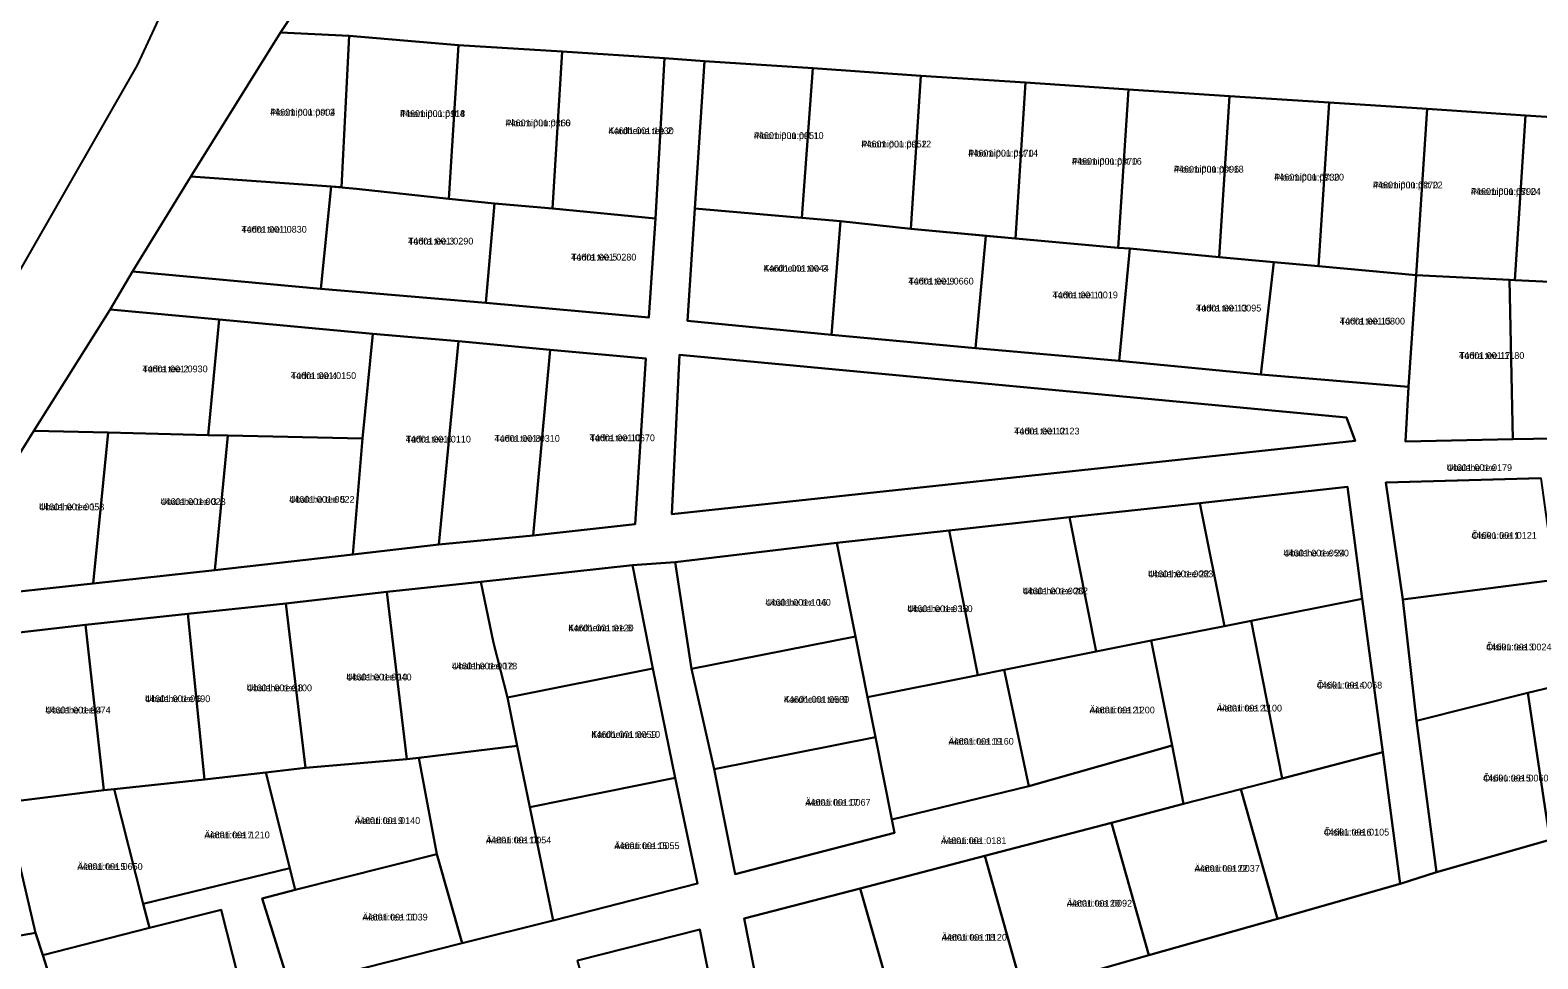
# Model space of a CAD drawing. Extents: x 551843 to 558501, y 6589003 to 6595718.
# Drawn here: x 552686.3 to 553021.3, y 6594140 to 6594346.2 of the extents above; entities that cross this region are included whole.
import ezdxf

# ---------------------------------------------------------------- set-up
doc = ezdxf.new("R2010")
doc.units = 0
for name, color, linetype in [('L_AADRESS', 7, 'Continuous'), ('PIIR', 7, 'Continuous'), ('TUNNUS', 7, 'Continuous')]:
    doc.layers.add(name, color=color, linetype=linetype)

msp = doc.modelspace()

# ---------------------------------------------------------------- linework, layer by layer
at = {"layer": 'PIIR'}
for points in [[(552676.63, 6594279.98), (552710.18, 6594338.44), (552745.65, 6594415), (552793.72, 6594491.36), (552795.61, 6594502.88), (552792.17, 6594519.71), (552781.04, 6594550.55), (552814.3, 6594546.07), (552818.23, 6594527.03), (552823.06, 6594503.42), (552821.12, 6594491.82), (552810.12, 6594492.3), (552808.89, 6594461.57), (552795.93, 6594432.53), (552789.98, 6594427.46), (552788.3, 6594424.19), (552772.33, 6594393.24), (552758.25, 6594370.36), (552741.94, 6594345.71), (552722.08, 6594313.72), (552709.1, 6594292.61), (552704.13, 6594284.19), (552687.17, 6594257.22), (552674.48, 6594236.93)], [(553194.56, 6594276.53), (553173.93, 6594295.82), (553163.41, 6594306.08), (553147.91, 6594313.18), (553121.76, 6594320.3), (553090.15, 6594322.85), (553081.55, 6594323.18), (553062.89, 6594324.4), (553040.63, 6594325.85), (553018.57, 6594327.29), (552996.74, 6594328.72), (552974.97, 6594330.15), (552952.85, 6594331.6), (552930.37, 6594333.07), (552907.51, 6594334.57), (552884.27, 6594336.09), (552860.25, 6594337.8), (552836.15, 6594339.37), (552827.27, 6594340.04), (552804.55, 6594341.5), (552781.49, 6594342.87), (552757.25, 6594344.93), (552741.94, 6594345.71), (552758.25, 6594370.36)], [(552672.97, 6594220.35), (552700.37, 6594223.36), (552727.41, 6594226.33), (552758.07, 6594229.78), (552777.16, 6594232.02), (552798.13, 6594234.04), (552820.77, 6594236.53), (552823.17, 6594273.31), (552801.89, 6594275.26), (552781.48, 6594277.15), (552762.5, 6594278.78), (552728.31, 6594281.97), (552704.13, 6594284.19), (552709.1, 6594292.61), (552750.9, 6594288.79), (552787.58, 6594285.7), (552823.82, 6594282.39), (552825.3, 6594304.42), (552827.27, 6594340.04), (552836.15, 6594339.37), (552834.01, 6594306.61), (552832.38, 6594281.68), (552864.38, 6594278.57), (552896.38, 6594275.64), (552928.3, 6594272.79), (552959.79, 6594269.78), (552992.57, 6594267.01), (552991.89, 6594254.86), (553015.76, 6594255.38), (553038.61, 6594255.8)], [(553021.95, 6594246.77), (552987.53, 6594245.76), (552991.31, 6594219.76), (552994.34, 6594192.86), (552998.81, 6594159.24), (552990.77, 6594156.63), (552986.85, 6594185.88), (552982.31, 6594219.97), (552979.01, 6594244.8), (552946.25, 6594241.21), (552917.26, 6594238.04), (552890.52, 6594235.11), (552865.58, 6594232.37), (552829.65, 6594228.1), (552820.14, 6594227.42), (552786.48, 6594223.71), (552765.56, 6594221.47), (552743.13, 6594218.88), (552721.39, 6594216.61), (552698.65, 6594214.16), (552676.78, 6594211.68)], [(552733.81, 6594131.03), (552728.76, 6594150.9), (552712.85, 6594146.86), (552711.49, 6594152.19), (552744.01, 6594160.13), (552745.23, 6594155.3), (552737.93, 6594153.38), (552744.04, 6594133.78), (552782.31, 6594143.47), (552802.57, 6594148.5), (552834.58, 6594156.74), (552829.69, 6594180.22), (552824.71, 6594204.46), (552820.14, 6594227.42), (552829.65, 6594228.1), (552833.25, 6594204.43), (552838.35, 6594182.13), (552842.99, 6594158.76), (552878.37, 6594167.95), (552877.79, 6594170.9), (552908.22, 6594178.34), (552940.07, 6594187.35), (552942.6, 6594174.38), (552926.59, 6594170.18), (552898.42, 6594162.84), (552870.79, 6594155.65), (552844.95, 6594148.93), (552851.28, 6594117.04)], [(552673.17, 6594066.67), (552696.67, 6594073.28), (552719.97, 6594079.85), (552744.27, 6594086.95), (552767.72, 6594093.6), (552792.38, 6594100.78), (552817.06, 6594107.42), (552841.54, 6594114.37), (552851.28, 6594117.04), (552879.47, 6594125.05), (552906.93, 6594132.82), (552934.92, 6594140.78), (552963.51, 6594148.89), (552990.77, 6594156.63), (552998.81, 6594159.24), (553024.01, 6594166.39)], [(552841.54, 6594114.37), (552835.14, 6594146.54), (552807.92, 6594139.61)]]:
    msp.add_lwpolyline(points, dxfattribs=at)
for points in [[(552757.25, 6594344.93), (552755.53, 6594311.35), (552753.23, 6594311.53), (552722.08, 6594313.72), (552741.94, 6594345.71)], [(552757.25, 6594344.93), (552781.49, 6594342.87), (552779.38, 6594308.8), (552758.89, 6594310.97), (552755.53, 6594311.3)], [(552804.55, 6594341.5), (552802.39, 6594306.6), (552789.5, 6594307.74), (552779.38, 6594308.8), (552781.49, 6594342.87)], [(552827.27, 6594340.04), (552825.3, 6594304.42), (552802.39, 6594306.6), (552804.55, 6594341.5)], [(552860.25, 6594337.8), (552857.79, 6594304.58), (552834.01, 6594306.61), (552836.15, 6594339.37)], [(552884.27, 6594336.09), (552882.05, 6594302.09), (552866.41, 6594303.84), (552857.79, 6594304.58), (552860.25, 6594337.8)], [(552907.51, 6594334.57), (552905.25, 6594299.97), (552882.05, 6594302.09), (552884.27, 6594336.09)], [(552930.37, 6594333.07), (552928.08, 6594297.88), (552905.25, 6594299.97), (552907.51, 6594334.57)], [(552930.37, 6594333.07), (552952.85, 6594331.6), (552950.53, 6594295.83), (552930.68, 6594297.71), (552928.08, 6594297.88)], [(552974.97, 6594330.15), (552972.61, 6594293.79), (552962.67, 6594294.71), (552950.53, 6594295.83), (552952.85, 6594331.6)], [(552996.74, 6594328.72), (552994.32, 6594291.8), (552972.61, 6594293.79), (552974.97, 6594330.15)], [(552996.74, 6594328.72), (553018.57, 6594327.29), (553016.18, 6594290.73), (553014.99, 6594290.79), (552994.32, 6594291.8)], [(553040.63, 6594325.85), (553037.95, 6594289.67), (553016.18, 6594290.73), (553018.57, 6594327.29)], [(552753.23, 6594311.53), (552750.9, 6594288.79), (552709.1, 6594292.61), (552722.08, 6594313.72)], [(552758.84, 6594310.96), (552779.38, 6594308.8), (552789.5, 6594307.74), (552787.58, 6594285.7), (552750.9, 6594288.79), (552753.23, 6594311.53)], [(552789.5, 6594307.74), (552802.39, 6594306.6), (552825.3, 6594304.42), (552823.82, 6594282.39), (552787.58, 6594285.7)], [(552857.79, 6594304.58), (552866.41, 6594303.84), (552864.38, 6594278.57), (552832.38, 6594281.68), (552834.01, 6594306.61)], [(552864.38, 6594278.57), (552866.41, 6594303.84), (552882.05, 6594302.09), (552898.67, 6594300.57), (552896.38, 6594275.64)], [(552905.25, 6594299.97), (552928.08, 6594297.88), (552930.68, 6594297.71), (552928.3, 6594272.79), (552896.38, 6594275.64), (552898.67, 6594300.57)], [(552959.79, 6594269.78), (552928.3, 6594272.79), (552930.68, 6594297.71), (552950.53, 6594295.83), (552962.67, 6594294.71)], [(552962.67, 6594294.71), (552972.61, 6594293.79), (552994.32, 6594291.8), (552992.57, 6594267.01), (552959.79, 6594269.78)], [(552992.57, 6594267.01), (552994.32, 6594291.8), (553014.99, 6594290.79), (553015.76, 6594255.38), (552991.89, 6594254.86)], [(553038.61, 6594255.8), (553015.76, 6594255.38), (553014.99, 6594290.79), (553016.18, 6594290.73), (553037.95, 6594289.67)], [(552728.31, 6594281.97), (552725.87, 6594256.31), (552703.67, 6594256.84), (552687.17, 6594257.22), (552704.13, 6594284.19)], [(552762.5, 6594278.78), (552760.2, 6594255.58), (552730.23, 6594256.22), (552725.87, 6594256.31), (552728.31, 6594281.97)], [(552760.2, 6594255.58), (552762.5, 6594278.78), (552781.48, 6594277.15), (552777.16, 6594232.02), (552758.07, 6594229.78)], [(552801.89, 6594275.26), (552798.13, 6594234.04), (552777.16, 6594232.02), (552781.48, 6594277.15)], [(552801.89, 6594275.26), (552823.17, 6594273.31), (552820.77, 6594236.53), (552798.13, 6594234.04)], [(552830.59, 6594274.16), (552978.83, 6594260.19), (552980.77, 6594255.05), (552828.88, 6594238.72)], [(552978.83, 6594260.19), (552830.59, 6594274.16), (552828.88, 6594238.72), (552980.77, 6594255.05)], [(552672.97, 6594220.35), (552674.48, 6594236.93), (552687.17, 6594257.22), (552703.67, 6594256.84), (552700.37, 6594223.36)], [(552725.87, 6594256.31), (552730.23, 6594256.22), (552727.41, 6594226.33), (552700.37, 6594223.36), (552703.67, 6594256.84)], [(552760.2, 6594255.58), (552758.07, 6594229.78), (552727.41, 6594226.33), (552730.23, 6594256.22)], [(552979.01, 6594244.8), (552982.31, 6594219.97), (552957.61, 6594215.07), (552951.68, 6594213.9), (552946.25, 6594241.21)], [(552987.53, 6594245.76), (553021.96, 6594246.77), (553025.11, 6594224.15), (552991.31, 6594219.76)], [(552917.26, 6594238.04), (552946.25, 6594241.21), (552951.68, 6594213.9), (552935.41, 6594210.67), (552923.19, 6594208.24)], [(552890.52, 6594235.11), (552917.26, 6594238.04), (552923.19, 6594208.24), (552902.74, 6594204.17), (552896.9, 6594203.01)], [(552890.52, 6594235.11), (552896.9, 6594203.01), (552872.38, 6594198.13), (552869.71, 6594211.57), (552865.58, 6594232.37)], [(552865.58, 6594232.37), (552869.71, 6594211.57), (552833.25, 6594204.43), (552829.65, 6594228.1)], [(552786.48, 6594223.71), (552820.14, 6594227.42), (552824.71, 6594204.46), (552792.37, 6594198.02), (552789.32, 6594210.14)], [(552747.53, 6594182.4), (552743.13, 6594218.88), (552765.56, 6594221.47), (552770.04, 6594184.35)], [(552765.56, 6594221.47), (552786.48, 6594223.71), (552789.32, 6594210.14), (552792.37, 6594198.02), (552794.55, 6594187.33), (552772.69, 6594184.6), (552770.04, 6594184.35)], [(553025.11, 6594224.15), (553028.07, 6594201.21), (553019.07, 6594199.06), (552994.34, 6594192.86), (552991.3, 6594219.76)], [(552725.06, 6594179.83), (552721.39, 6594216.61), (552743.13, 6594218.88), (552747.53, 6594182.4), (552738.68, 6594181.34)], [(552982.31, 6594219.97), (552986.85, 6594185.88), (552964.55, 6594180.07), (552957.61, 6594215.07)], [(552702.68, 6594177.45), (552698.65, 6594214.16), (552721.39, 6594216.61), (552725.06, 6594179.83), (552705.01, 6594177.7)], [(552964.55, 6594180.07), (552955.34, 6594177.67), (552942.6, 6594174.38), (552940.07, 6594187.35), (552935.41, 6594210.67), (552951.68, 6594213.9), (552957.61, 6594215.07)], [(552676.78, 6594211.68), (552698.65, 6594214.16), (552702.68, 6594177.45), (552680.82, 6594174.7)], [(552833.25, 6594204.43), (552869.71, 6594211.57), (552872.38, 6594198.13), (552874.15, 6594189.23), (552838.35, 6594182.13)], [(552902.74, 6594204.17), (552923.19, 6594208.24), (552935.41, 6594210.67), (552940.07, 6594187.35), (552908.22, 6594178.34)], [(552829.69, 6594180.22), (552797.33, 6594173.68), (552794.55, 6594187.33), (552792.37, 6594198.02), (552824.71, 6594204.46)], [(553044.55, 6594205.86), (553049.43, 6594173.62), (553024.01, 6594166.39), (553019.07, 6594199.06), (553028.07, 6594201.21)], [(552874.15, 6594189.23), (552872.38, 6594198.13), (552896.9, 6594203.01), (552902.74, 6594204.17), (552908.22, 6594178.34), (552877.79, 6594170.9)], [(553019.07, 6594199.06), (553024.01, 6594166.39), (552998.81, 6594159.24), (552994.34, 6594192.86)], [(552878.37, 6594167.95), (552842.99, 6594158.76), (552838.35, 6594182.13), (552874.15, 6594189.23), (552877.79, 6594170.9)], [(552738.68, 6594181.34), (552747.53, 6594182.4), (552770.04, 6594184.35), (552772.69, 6594184.6), (552776.72, 6594163.24), (552745.23, 6594155.3), (552744.01, 6594160.13)], [(552794.55, 6594187.33), (552797.33, 6594173.68), (552802.57, 6594148.5), (552782.31, 6594143.47), (552776.72, 6594163.24), (552772.69, 6594184.6)], [(552986.85, 6594185.88), (552990.77, 6594156.63), (552963.51, 6594148.89), (552955.34, 6594177.67), (552964.55, 6594180.07)], [(552705.01, 6594177.7), (552725.06, 6594179.83), (552738.68, 6594181.34), (552744.01, 6594160.13), (552711.49, 6594152.19)], [(552712.85, 6594146.86), (552689.15, 6594140.83), (552687.57, 6594145.78), (552680.82, 6594174.7), (552702.68, 6594177.45), (552705.01, 6594177.7), (552711.49, 6594152.19)], [(552834.58, 6594156.74), (552802.57, 6594148.5), (552797.33, 6594173.68), (552829.69, 6594180.22)], [(552934.92, 6594140.78), (552926.59, 6594170.18), (552942.6, 6594174.38), (552955.34, 6594177.67), (552963.51, 6594148.89)], [(552654.56, 6594171.82), (552680.82, 6594174.7), (552687.57, 6594145.78), (552656.59, 6594140.38)], [(552934.92, 6594140.78), (552906.93, 6594132.82), (552898.42, 6594162.84), (552926.59, 6594170.18)], [(552744.04, 6594133.78), (552737.93, 6594153.38), (552745.23, 6594155.3), (552776.72, 6594163.24), (552782.31, 6594143.47)], [(552870.79, 6594155.65), (552898.42, 6594162.84), (552906.93, 6594132.82), (552879.47, 6594125.05)], [(552851.28, 6594117.04), (552844.95, 6594148.93), (552870.79, 6594155.65), (552879.47, 6594125.05)], [(552693.91, 6594121.23), (552691.97, 6594130.39), (552690.05, 6594138), (552689.15, 6594140.83), (552712.85, 6594146.86), (552728.76, 6594150.9), (552733.81, 6594131.03)], [(552660.85, 6594112.25), (552656.59, 6594140.38), (552687.57, 6594145.78), (552689.15, 6594140.83), (552690.05, 6594138), (552691.97, 6594130.39), (552693.91, 6594121.23)], [(552835.14, 6594146.54), (552841.54, 6594114.37), (552817.06, 6594107.42), (552807.92, 6594139.61)]]:
    msp.add_lwpolyline(points, close=True, dxfattribs=at)

# ---------------------------------------------------------------- texts
at = {"layer": 'L_AADRESS'}
for s, p in [('Ploomipuu pst 2', (552739.66, 6594327.26)), ('Ploomipuu pst 4', (552768.51, 6594326.96)), ('Ploomipuu pst 6', (552791.96, 6594324.88)), ('Kardheina tee 2', (552814.83, 6594323.13)), ('Ploomipuu pst 10', (552847.13, 6594322.07)), ('Ploomipuu pst 12', (552871.03, 6594320.18)), ('Ploomipuu pst 14', (552894.78, 6594318.16)), ('Ploomipuu pst 16', (552917.81, 6594316.36)), ('Ploomipuu pst 18', (552940.46, 6594314.6)), ('Ploomipuu pst 20', (552962.75, 6594312.83)), ('Ploomipuu pst 22', (552984.68, 6594311.1)), ('Ploomipuu pst 24', (553006.45, 6594309.65)), ('Tudra tee 1', (552733.3, 6594301.25)), ('Tudra tee 3', (552770.31, 6594298.62)), ('Tudra tee 5', (552806.53, 6594295.07)), ('Kardheina tee 3', (552849.3, 6594292.59)), ('Tudra tee 9', (552881.48, 6594289.74)), ('Tudra tee 11', (552913.51, 6594286.68)), ('Tudra tee 13', (552945.37, 6594283.75)), ('Tudra tee 15', (552977.31, 6594280.86)), ('Tudra tee 17', (553003.82, 6594273.23)), ('Tudra tee 2', (552711.28, 6594270.25)), ('Tudra tee 4', (552744.28, 6594268.77)), ('Tudra tee 12', (552904.99, 6594256.44)), ('Tudra tee 6', (552769.77, 6594254.65)), ('Tudra tee 8', (552789.52, 6594254.81)), ('Tudra tee 10', (552810.65, 6594254.94)), ('Ubalehe tee', (553001.09, 6594248.33)), ('Ubalehe tee 1', (552688.32, 6594239.61)), ('Ubalehe tee 3', (552715.3, 6594240.78)), ('Ubalehe tee 5', (552743.92, 6594241.27)), ('Õisiku tee 1', (553006.59, 6594233.27)), ('Ubalehe tee 24', (552964.84, 6594229.35)), ('Ubalehe tee 22', (552934.72, 6594224.73)), ('Ubalehe tee 20', (552906.86, 6594220.94)), ('Ubalehe tee 16', (552849.74, 6594218.4)), ('Ubalehe tee 18', (552881.24, 6594216.99)), ('Kardheina tee 8', (552805.92, 6594212.72)), ('Õisiku tee 3', (553009.85, 6594208.5)), ('Ubalehe tee 12', (552780.05, 6594204.27)), ('Ubalehe tee 8', (552734.46, 6594199.42)), ('Ubalehe tee 10', (552756.59, 6594201.81)), ('Õisiku tee 4', (552972.23, 6594200.02)), ('Ubalehe tee 6', (552711.86, 6594197)), ('Kardheina tee 9', (552853.81, 6594196.85)), ('Ubalehe tee 4', (552689.73, 6594194.48)), ('Äiatari tee 21', (552921.72, 6594194.51)), ('Äiatari tee 23', (552949.98, 6594194.92)), ('Kardheina tee 10', (552811.03, 6594189.07)), ('Äiatari tee 19', (552890.38, 6594187.54)), ('Õisiku tee 5', (553009.18, 6594179.38)), ('Äiatari tee 17', (552858.57, 6594174)), ('Äiatari tee 9', (552758.5, 6594169.95)), ('Äiatari tee 7', (552725.07, 6594166.77)), ('Äiatari tee 13', (552787.63, 6594165.63)), ('Õisiku tee 6', (552973.79, 6594167.38)), ('Äiatari tee 15', (552816.13, 6594164.36)), ('Äiatari tee', (552888.73, 6594165.49)), ('Äiatari tee 5', (552696.84, 6594159.75)), ('Äiatari tee 22', (552945.05, 6594159.33)), ('Äiatari tee 20', (552916.67, 6594151.59)), ('Äiatari tee 11', (552760.17, 6594148.51)), ('Äiatari tee 18', (552888.86, 6594144.03))]:
    msp.add_text(s, height=1.5, dxfattribs=at).set_placement(p)
at = {"layer": 'TUNNUS'}
for s, p in [('44601:001:0004', (552739.66, 6594327.26)), ('44601:001:0118', (552768.51, 6594326.96)), ('44601:001:0260', (552791.96, 6594324.88)), ('44601:001:1030', (552814.83, 6594323.13)), ('44601:001:0051', (552847.13, 6594322.07)), ('44601:001:0052', (552871.03, 6594320.18)), ('44601:001:0170', (552894.78, 6594318.16)), ('44601:001:0370', (552917.81, 6594316.36)), ('44601:001:0096', (552940.46, 6594314.6)), ('44601:001:0730', (552962.75, 6594312.83)), ('44601:001:0270', (552984.68, 6594311.1)), ('44601:001:0790', (553006.45, 6594309.65)), ('44601:001:0830', (552733.3, 6594301.25)), ('44601:001:0290', (552770.31, 6594298.62)), ('44601:001:0280', (552806.53, 6594295.07)), ('44601:001:0044', (552849.3, 6594292.59)), ('44601:001:0660', (552881.48, 6594289.74)), ('44601:001:0019', (552913.51, 6594286.68)), ('44601:001:0095', (552945.37, 6594283.75)), ('44601:001:0800', (552977.31, 6594280.86)), ('44601:001:1180', (553003.82, 6594273.23)), ('44601:001:0930', (552711.28, 6594270.25)), ('44601:001:0150', (552744.28, 6594268.77)), ('44601:001:0123', (552904.99, 6594256.44)), ('44601:001:0110', (552769.77, 6594254.65)), ('44601:001:0310', (552789.52, 6594254.81)), ('44601:001:0670', (552810.65, 6594254.94)), ('44601:001:0179', (553001.09, 6594248.33)), ('44601:001:0023', (552715.3, 6594240.78)), ('44601:001:0022', (552743.92, 6594241.27)), ('44601:001:0058', (552688.32, 6594239.61)), ('44601:001:0121', (553006.59, 6594233.27)), ('44601:001:0590', (552964.84, 6594229.35)), ('44601:001:0083', (552934.72, 6594224.73)), ('44601:001:0082', (552906.86, 6594220.94)), ('44601:001:1040', (552849.74, 6594218.4)), ('44601:001:0350', (552881.24, 6594216.99)), ('44601:001:0120', (552805.92, 6594212.72)), ('44601:001:0024', (553009.85, 6594208.5)), ('44601:001:0078', (552780.05, 6594204.27)), ('44601:001:0040', (552756.59, 6594201.81)), ('44601:001:0068', (552972.23, 6594200.02)), ('44601:001:0490', (552711.86, 6594197)), ('44601:001:0100', (552734.46, 6594199.42)), ('44601:001:0580', (552853.81, 6594196.85)), ('44601:001:0074', (552689.73, 6594194.48)), ('44601:001:1200', (552921.72, 6594194.51)), ('44601:001:1100', (552949.98, 6594194.92)), ('44601:001:0059', (552811.03, 6594189.07)), ('44601:001:1160', (552890.38, 6594187.54)), ('44601:001:0060', (553009.18, 6594179.38)), ('44601:001:0067', (552858.57, 6594174)), ('44601:001:0140', (552758.5, 6594169.95)), ('44601:001:1210', (552725.07, 6594166.77)), ('44601:001:0105', (552973.79, 6594167.38)), ('44601:001:0054', (552787.63, 6594165.63)), ('44601:001:0055', (552816.13, 6594164.36)), ('44601:001:0181', (552888.73, 6594165.49)), ('44601:001:0650', (552696.84, 6594159.75)), ('44601:001:0037', (552945.05, 6594159.33)), ('44601:001:0092', (552916.67, 6594151.59)), ('44601:001:0039', (552760.17, 6594148.51)), ('44601:001:1120', (552888.86, 6594144.03))]:
    msp.add_text(s, height=1.5, dxfattribs=at).set_placement(p)

doc.saveas('drawing.dxf')
